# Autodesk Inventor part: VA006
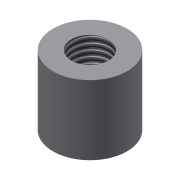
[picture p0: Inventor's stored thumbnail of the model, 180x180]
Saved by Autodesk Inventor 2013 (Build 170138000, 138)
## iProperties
Manager: P MOLLOY
Company: NUIG
Shininess: 64.0
Length Units: 11269
Angle Units: 11279
Time Units: 11290
Mass Units: 11283
Length Display Precision: 3
Angle Display Precision: 2
Compacted: True
Part Number: VA006
Document SubType Name: Modeling
Created: 2004-12
Designer: warren davies
Manufacturer: Standard
Standards Organization: Custom
Material: Generic
Density: 1 g/cm^3
Density: 0.0
Volumn: 0.0
Area: 0.0
PropertySet Name: Model Information
Control State: 0
Master: False
Checked Out: False
Title: HANDLE STOP
Subject: VICE ASSEMBLY
Author: warren davies
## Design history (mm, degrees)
sketch "Sketch1"
  geometry: C1 r 8 at (0, 0)
  constraints: 1 centre point
  dimensions: "d0" = 16 diameter of C1
extrude "Extrusion1" new body sketch "Sketch1" distance "d1" = 15; taper "d2" = 0 deg
sketch "Sketch2"
  geometry: C1 r 8 at (0, 0) reference; C2 r 4 at (0, 0)
  constraints: 1 centre point, 1 coincident
  dimensions: "d3" = 8 diameter of C2
extrude "Extrusion2" cut sketch "Sketch2" distance "d4" = 13; taper "d5" = 0 deg
thread "Thread1" dims "d6" = 10, "d7" = 0
body "Solid1"
